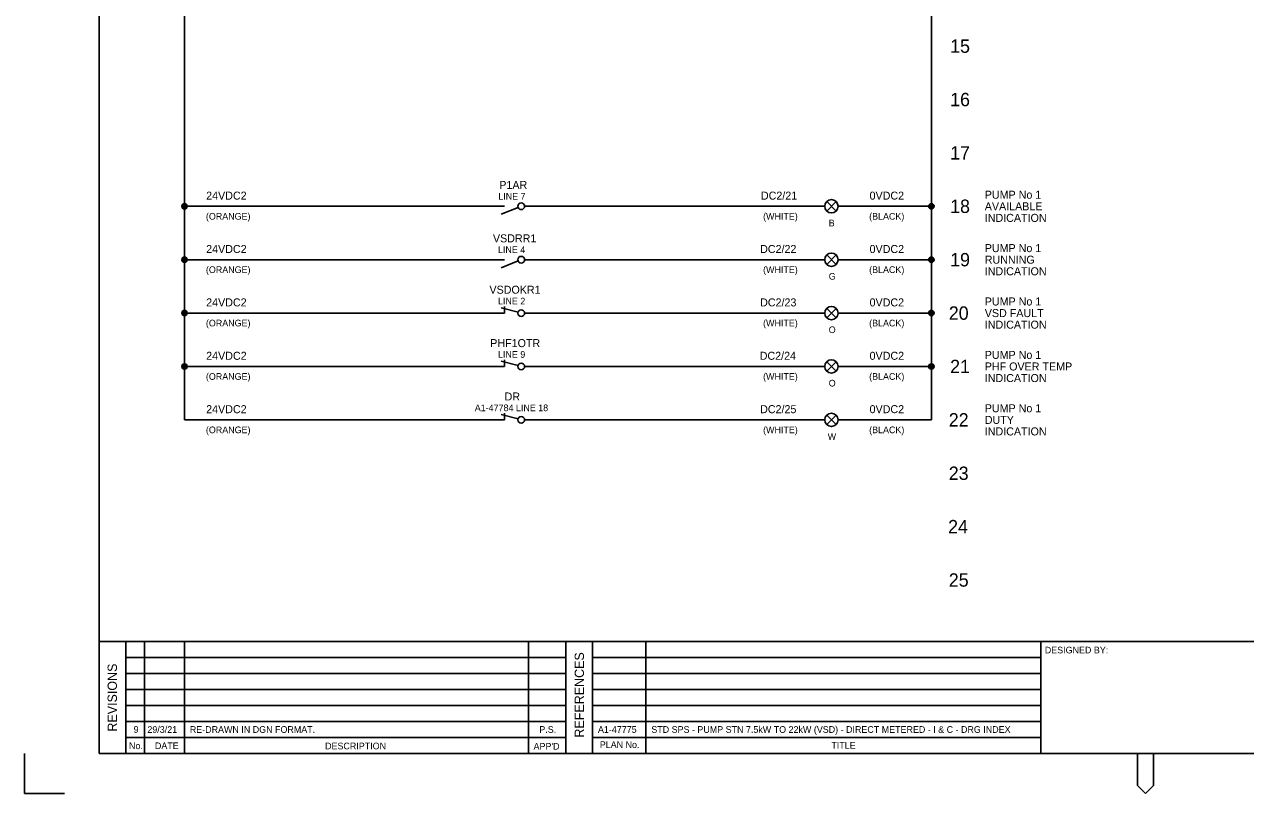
# Model space of a CAD drawing. Extents: x 0 to 841, y 0 to 594.
# Drawn here: x 0 to 457.8, y 0 to 288.1 of the extents above; entities that cross this region are included whole.
import ezdxf

# ---------------------------------------------------------------- set-up
doc = ezdxf.new("R2010")
doc.units = 0
for name, color, linetype in [('A1BORDER', 7, 'Continuous'), ('Level 1', 7, 'Continuous'), ('Level 10', 7, 'Continuous'), ('Level 5', 7, 'Continuous'), ('Level 6', 7, 'Continuous')]:
    doc.layers.add(name, color=color, linetype=linetype)

msp = doc.modelspace()

# ---------------------------------------------------------------- linework, layer by layer
at = {"layer": 'A1BORDER'}
for p, q in [((28, 581), (28, 15)), ((28, 57), (829, 57)), ((38, 15), (38, 57)), ((45, 15), (45, 57)), ((60, 15), (60, 57)), ((189, 15), (189, 57)), ((203, 15), (203, 57)), ((213, 15), (213, 57)), ((233, 15), (233, 57)), ((381, 15), (381, 57)), ((203, 51), (38, 51)), ((213, 51), (381, 51)), ((203, 45), (38, 45)), ((213, 45), (381, 45)), ((203, 39), (38, 39)), ((213, 39), (381, 39)), ((203, 33), (38, 33)), ((213, 33), (381, 33)), ((38, 27), (203, 27)), ((213, 27), (381, 27)), ((203, 21), (38, 21)), ((213, 21), (381, 21)), ((0, 0), (0, 15)), ((829, 15), (28, 15)), ((417.19, 15), (417.19, 3)), ((423.19, 15), (423.19, 3)), ((417.19, 3), (420.19, 0)), ((423.19, 3), (420.19, 0)), ((0, 0), (15, 0))]:
    msp.add_line(p, q, dxfattribs=at)
at = {"layer": 'Level 1'}
for p, q in [((60, 160), (60, 560)), ((340, 160), (340, 560)), ((60, 140), (60, 520)), ((340, 140), (340, 520)), ((60, 220), (177.5, 220)), ((180, 220), (177.5, 220)), ((177.5, 220), (177.5, 220)), ((187.5, 220), (187.5, 220)), ((305, 220), (340, 220)), ((60, 200), (177.5, 200)), ((180, 200), (177.5, 200)), ((177.5, 200), (177.5, 200)), ((187.5, 200), (187.5, 200)), ((305, 200), (340, 200)), ((60, 180), (177.5, 180)), ((180, 180), (177.5, 180)), ((305, 180), (340, 180)), ((60, 160), (177.5, 160)), ((180, 160), (177.5, 160)), ((305, 160), (340, 160)), ((60, 140), (177.5, 140)), ((180, 140), (177.5, 140)), ((305, 140), (340, 140))]:
    msp.add_line(p, q, dxfattribs=at)
at = {"layer": 'Level 10'}
for p, q in [((59.1, 220.44), (59.1, 219.56)), ((59.4, 220.8), (59.4, 219.2)), ((59.7, 220.95), (59.7, 219.05)), ((60, 221), (60, 219.01)), ((60.3, 220.95), (60.3, 219.05)), ((60.6, 220.8), (60.6, 219.2)), ((60.9, 220.44), (60.9, 219.56)), ((61, 220), (61, 220)), ((304.27, 221.77), (300.73, 218.23)), ((300.73, 221.77), (304.27, 218.23)), ((339.1, 220.44), (339.1, 219.56)), ((339.4, 220.8), (339.4, 219.2)), ((339.7, 220.95), (339.7, 219.05)), ((340, 221), (340, 219.01)), ((340.3, 220.95), (340.3, 219.05)), ((340.6, 220.8), (340.6, 219.2)), ((340.9, 220.44), (340.9, 219.56)), ((341, 220), (341, 220)), ((185.09, 219.54), (178.75, 217)), ((304.27, 201.77), (300.73, 198.23)), ((300.73, 201.77), (304.27, 198.23)), ((59.1, 200.44), (59.1, 199.56)), ((59.4, 200.8), (59.4, 199.2)), ((59.7, 200.95), (59.7, 199.05)), ((60, 201), (60, 199.01)), ((60.3, 200.95), (60.3, 199.05)), ((60.6, 200.8), (60.6, 199.2)), ((60.9, 200.44), (60.9, 199.56)), ((61, 200), (61, 200)), ((185.09, 199.54), (178.75, 197)), ((339.1, 200.44), (339.1, 199.56)), ((339.4, 200.8), (339.4, 199.2)), ((339.7, 200.95), (339.7, 199.05)), ((340, 201), (340, 199.01)), ((340.3, 200.95), (340.3, 199.05)), ((340.6, 200.8), (340.6, 199.2)), ((340.9, 200.44), (340.9, 199.56)), ((341, 200), (341, 200)), ((59.1, 180.44), (59.1, 179.56)), ((59.4, 180.8), (59.4, 179.2)), ((59.7, 180.95), (59.7, 179.05)), ((60, 181), (60, 179.01)), ((60.3, 180.95), (60.3, 179.05)), ((60.6, 180.8), (60.6, 179.2)), ((60.9, 180.44), (60.9, 179.56)), ((61, 180), (61, 180)), ((185.04, 180.32), (178.75, 182)), ((180, 182.5), (180, 180)), ((304.27, 181.77), (300.73, 178.23)), ((300.73, 181.77), (304.27, 178.23)), ((339.1, 180.44), (339.1, 179.56)), ((339.4, 180.8), (339.4, 179.2)), ((339.7, 180.95), (339.7, 179.05)), ((340, 181), (340, 179.01)), ((340.3, 180.95), (340.3, 179.05)), ((340.6, 180.8), (340.6, 179.2)), ((340.9, 180.44), (340.9, 179.56)), ((341, 180), (341, 180)), ((59.1, 160.44), (59.1, 159.56)), ((59.4, 160.8), (59.4, 159.2)), ((59.7, 160.95), (59.7, 159.05)), ((60, 161), (60, 159.01)), ((60.3, 160.95), (60.3, 159.05)), ((60.6, 160.8), (60.6, 159.2)), ((60.9, 160.44), (60.9, 159.56)), ((185.04, 160.32), (178.75, 162)), ((180, 162.5), (180, 160)), ((304.27, 161.77), (300.73, 158.23)), ((300.73, 161.77), (304.27, 158.23)), ((339.1, 160.44), (339.1, 159.56)), ((339.4, 160.8), (339.4, 159.2)), ((339.7, 160.95), (339.7, 159.05)), ((340, 161), (340, 159.01)), ((340.3, 160.95), (340.3, 159.05)), ((340.6, 160.8), (340.6, 159.2)), ((340.9, 160.44), (340.9, 159.56)), ((61, 160), (61, 160)), ((341, 160), (341, 160)), ((185.04, 140.32), (178.75, 142)), ((180, 142.5), (180, 140)), ((304.27, 141.77), (300.73, 138.23)), ((300.73, 141.77), (304.27, 138.23))]:
    msp.add_line(p, q, dxfattribs=at)
for centre, radius in [((60, 220), 1), ((186.25, 220), 1.25), ((302.5, 220), 2.5), ((340, 220), 1), ((302.5, 200), 2.5), ((60, 200), 1), ((186.25, 200), 1.25), ((340, 200), 1), ((60, 180), 1), ((186.25, 180), 1.25), ((302.5, 180), 2.5), ((340, 180), 1), ((60, 160), 1), ((186.25, 160), 1.25), ((302.5, 160), 2.5), ((340, 160), 1), ((302.5, 140), 2.5), ((186.25, 140), 1.25)]:
    msp.add_circle(centre, radius, dxfattribs=at)
at = {"layer": 'Level 6'}
for p, q in [((187.5, 220), (300, 220)), ((187.5, 200), (300, 200)), ((187.5, 180), (300, 180)), ((187.5, 160), (300, 160)), ((187.5, 140), (300, 140))]:
    msp.add_line(p, q, dxfattribs=at)

# ---------------------------------------------------------------- texts
at = {"layer": 'A1BORDER'}
for s, p in [('DESIGNED BY:', (382.5, 52.5)), ('No.', (39.21, 16.65)), ('DATE', (48.92, 16.65)), ('DESCRIPTION', (112.71, 16.57)), ("APP'D", (190.85, 16.44)), ('PLAN No.', (215.69, 17.06)), ('TITLE', (302.5, 16.81))]:
    msp.add_text(s, height=2.5, dxfattribs=at).set_placement(p)
for s, p in [('REFERENCES', (209.76, 20.96)), ('REVISIONS', (34.68, 23.2))]:
    msp.add_text(s, height=3.5, rotation=90, dxfattribs=at).set_placement(p)
at = {"layer": 'Level 1'}
for s, height, p in [('15', 5, (347.01, 277.5)), ('16', 5, (347.01, 257.5)), ('17', 5, (347.01, 237.5)), ('18', 5, (347.01, 217.5)), ('19', 5, (347.01, 197.5)), ('20', 5, (346.51, 177.5)), ('21', 5, (347.01, 157.5)), ('22', 5, (346.51, 137.5)), ('23', 5, (346.51, 117.5)), ('24', 5, (346.26, 97.5)), ('25', 5, (346.51, 77.5)), ('9', 2.5, (40.94, 22.75)), ('29/3/21', 2.5, (46.09, 22.75)), ('RE-DRAWN IN DGN FORMAT.', 2.5, (62, 22.75)), ('P.S.', 2.5, (193.02, 22.75)), ('A1-47775', 2.5, (215, 22.75)), ('STD SPS - PUMP STN 7.5kW TO 22kW (VSD) - DIRECT METERED - I & C - DRG INDEX', 2.5, (235, 22.75))]:
    msp.add_text(s, height=height, dxfattribs=at).set_placement(p)
at = {"layer": 'Level 5'}
for s, height, p in [('P1AR', 3, (178.02, 226.5)), ('24VDC2', 3, (68.13, 222.5)), ('LINE 7', 2.5, (177.64, 222.5)), ('DC2/21', 3, (276.08, 222.5)), ('0VDC2', 3, (316.82, 222.5)), ('PUMP No 1', 3, (360, 222.84)), ('AVAILABLE', 3, (360, 218.5)), ('(ORANGE)', 2.5, (68.03, 215)), ('(WHITE)', 2.5, (276.9, 215)), ('(BLACK)', 2.5, (316.65, 215)), ('INDICATION', 3, (360, 214.16)), ('B', 2.5, (301.5, 212.5)), ('VSDRR1', 3, (175.63, 206.5)), ('24VDC2', 3, (68.13, 202.5)), ('LINE 4', 2.5, (177.52, 202.5)), ('DC2/22', 3, (275.78, 202.5)), ('0VDC2', 3, (316.82, 202.5)), ('PUMP No 1', 3, (360, 202.84)), ('RUNNING', 3, (360, 198.5)), ('(ORANGE)', 2.5, (68.03, 195)), ('(WHITE)', 2.5, (276.9, 195)), ('(BLACK)', 2.5, (316.65, 195)), ('INDICATION', 3, (360, 194.16)), ('G', 2.5, (301.5, 192.5)), ('VSDOKR1', 3, (174.32, 187.25)), ('24VDC2', 3, (68.13, 182.5)), ('LINE 2', 2.5, (177.53, 183.25)), ('DC2/23', 3, (275.78, 182.5)), ('0VDC2', 3, (316.82, 182.5)), ('PUMP No 1', 3, (360, 182.84)), ('VSD FAULT', 3, (360, 178.5)), ('(ORANGE)', 2.5, (68.03, 175)), ('(WHITE)', 2.5, (276.9, 175)), ('O', 2.5, (301.5, 172.5)), ('(BLACK)', 2.5, (316.65, 175)), ('INDICATION', 3, (360, 174.16)), ('PHF1OTR', 3, (174.62, 167.25)), ('24VDC2', 3, (68.13, 162.5)), ('LINE 9', 2.5, (177.53, 163.25)), ('DC2/24', 3, (275.63, 162.5)), ('0VDC2', 3, (316.82, 162.5)), ('PUMP No 1', 3, (360, 162.84)), ('PHF OVER TEMP', 3, (360, 158.5)), ('(ORANGE)', 2.5, (68.03, 155)), ('(WHITE)', 2.5, (276.9, 155)), ('(BLACK)', 2.5, (316.65, 155)), ('INDICATION', 3, (360, 154.16)), ('O', 2.5, (301.5, 152.5)), ('DR', 3, (180, 147.25)), ('24VDC2', 3, (68.13, 142.5)), ('A1-47784 LINE 18', 2.5, (168.82, 143.25)), ('DC2/25', 3, (275.78, 142.5)), ('0VDC2', 3, (316.82, 142.5)), ('PUMP No 1', 3, (360, 142.84)), ('(ORANGE)', 2.5, (68.03, 135)), ('(WHITE)', 2.5, (276.9, 135)), ('(BLACK)', 2.5, (316.65, 135)), ('DUTY', 3, (360, 138.5)), ('W', 2.5, (301.13, 132.5)), ('INDICATION', 3, (360, 134.16))]:
    msp.add_text(s, height=height, dxfattribs=at).set_placement(p)

doc.saveas('drawing.dxf')
